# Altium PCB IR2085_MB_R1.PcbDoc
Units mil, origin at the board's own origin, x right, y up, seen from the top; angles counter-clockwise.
Board outline 6000 x 4000 mil, 2 copper layers (Top Layer, Bottom Layer); 79 components, 34 nets, 245 pads, 204 vias.
Unrouted connection lines stored in the file: 2.
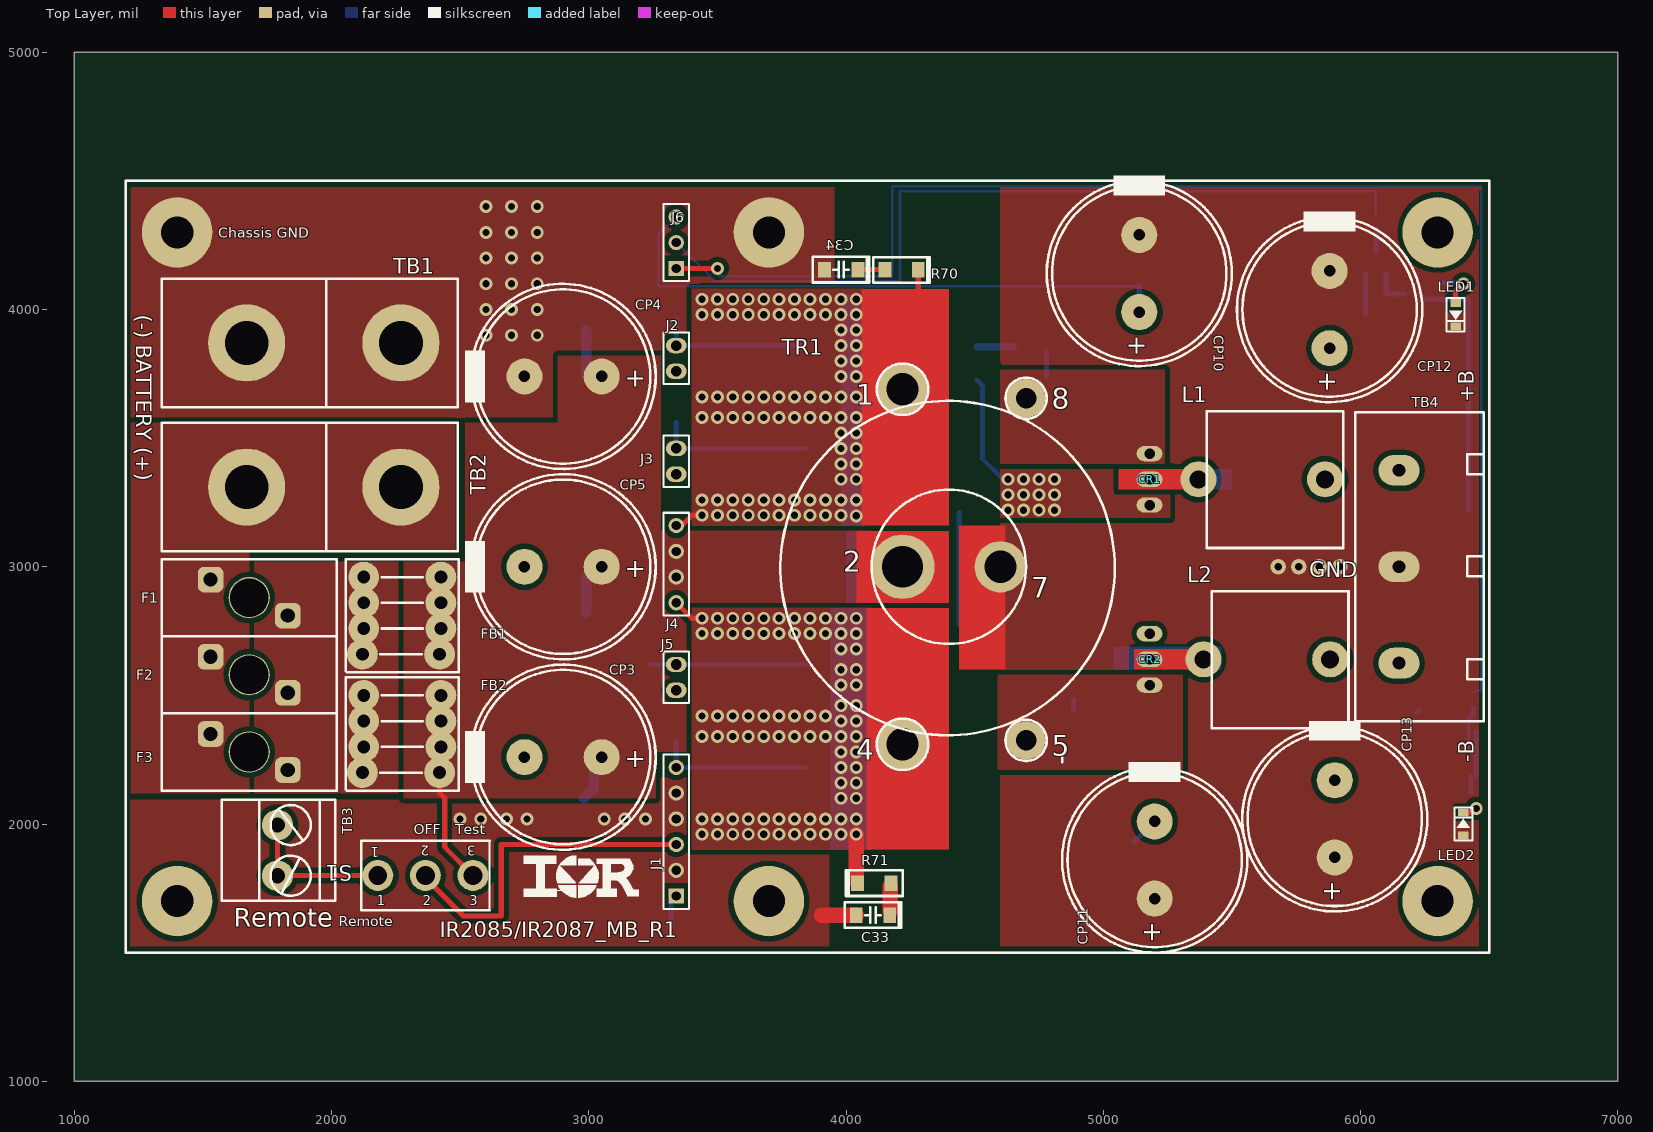
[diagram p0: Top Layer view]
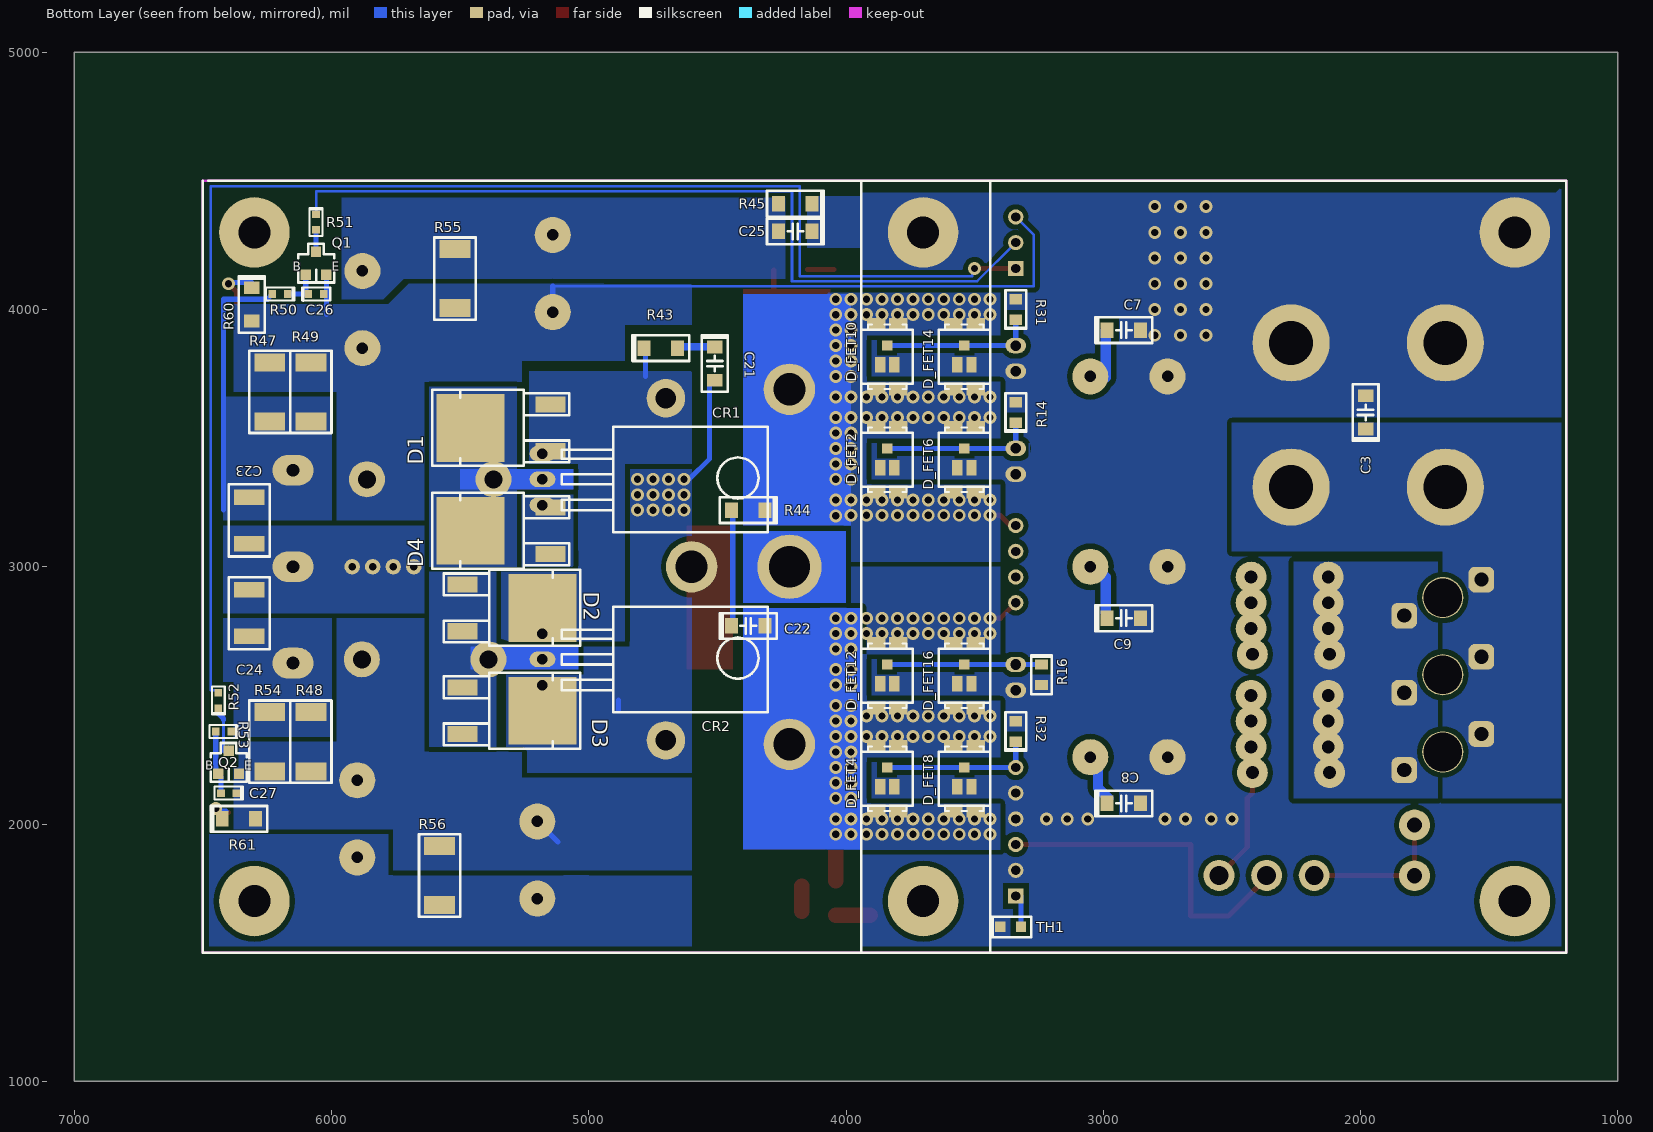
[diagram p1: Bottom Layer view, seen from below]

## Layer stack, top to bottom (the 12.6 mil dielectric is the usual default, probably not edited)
Top Layer: signal copper 1.4
Dielectric: dielectric 12.6, FR-4, Dk 4.8
Bottom Layer: signal copper 1.4

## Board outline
1000,1000 7000,1000 7000,5000 1000,5000

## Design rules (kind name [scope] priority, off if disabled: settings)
Clearance [All] p1: gap=20
ComponentClearance [All] p1: gap=10 collisioncheckmode=3 verticalgap=10
PlaneConnect [All] p1: planeconnectstyle=Direct reliefexpansion=20 reliefentries=4 reliefconductorwidth=10 reliefairgap=10
PolygonConnect [All] p1: connectstyle=Direct reliefconductorwidth=10 reliefentries=4 polygonreliefangle="90 Angle"
RoutingVias [All] p1: holewidth=28 width=38 viastyle="Through Hole" minholewidth=28 minwidth=38 maxholewidth=28 maxwidth=50
SolderMaskExpansion [All] p1: expansion=4
TestPointUsage [All] p1: valid=0 allowmultiple=FALSE
Testpoint [All] p1: side=15 testpointundercomponent=TRUE minsize=40 maxsize=100 preferedsize=60 minholesize=0 maxholesize=40 preferedholesize=32 testpointgrid=1 style=1023 order=0-112345678
Width [All] p1: maxlimit=40 minlimit=10 preferedwidth=20 toplayer_maxwidth=30 bottomlayer_maxwidth=30 minimp=50.000000 maximp=50.000000 favimp=50.000000
17 further rules are at their usual default settings.

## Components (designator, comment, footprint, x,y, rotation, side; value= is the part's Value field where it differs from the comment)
C3 "1uF" C-1206#1 1980,3600 r0 bottom
C7 "1uF" C-1206#1 2920,3920 r90 bottom
C8 "1uF" C-1206#1 2920,2080 r90 bottom
C9 "1uF" C-1206#1 2920,2800 r90 bottom (schematic designator C18)
C21 "C-1206" C-1206#1 4510,3790 r180 bottom
C22 "C-1206" C-1206#1 4380,2770 r90 bottom
C23 "1uF" 1812 6320,3180 r270 bottom
C24 "1uF" 1812 6320,2820 r270 bottom
C25 "C-1206" C-1206#1 4197,4304 r270 bottom
C26 "C-603" C-603 6060,4060 r90 bottom
C27 "C-603" C-603 6400,2120 r270 bottom
C33 "C-1206" C-1206#1 4105,1646 r270 top
C34 "C-1206" C-1206#2 3981,4155 r90 top
CP3 "CP7.5MMX16D" CP7.5MMX18D 2900,2260 r270 top
CP4 "CP7.5MMX16D" CP7.5MMX18D 2900,3740 r270 top
CP5 "CP7.5MMX16D" CP7.5MMX18D 2900,3000 r270 top
CP10 "CP7.5MMX18DX31H" CP7.5MMX18D 5140,4140 r180 top
CP11 "CP7.5MMX18DX31H" CP7.5MMX18D 5200,1860 r180 top
CP12 "CP7.5MMX18DX31H" CP7.5MMX18D 5880,4000 r180 top
CP13 "CP7.5MMX18DX31H" CP7.5MMX18D 5900,2020 r180 top
CR1 "TO220+RECT" TO220+RECT_BOT 5180,3340 r90 top
CR2 "TO220-RECT" TO220+RECT_BOT 5180,2640 r90 top
D1 "Dual Diode" "DPAK (TO-252)" 5460,3540 r90 bottom
D2 "Dual Diode" "DPAK (TO-252)" 5180,2840 r270 bottom
D3 "Dual Diode" "DPAK (TO-252)" 5180,2440 r270 bottom
D4 "Dual Diode" "DPAK (TO-252)" 5460,3140 r90 bottom
D_FET2 "IRF6648" IRF6648 3840,3420 r0 bottom
D_FET4 "IRF6648" IRF6648 3840,2180 r0 bottom
D_FET6 "IRF6648" IRF6648 3540,3420 r0 bottom
D_FET8 "IRF6648" IRF6648 3540,2180 r0 bottom
D_FET10 "IRF6648" IRF6648 3840,3820 r0 bottom
D_FET12 "IRF6648" IRF6648 3840,2580 r0 bottom
D_FET14 "IRF6648" IRF6648 3540,3820 r0 bottom
D_FET16 "IRF6648" IRF6648 3540,2580 r0 bottom
F1 "20A" FUSE-F065-ND_FUSE-F065-ND(Primary)#1 1680,2880 r90 top
F2 "20A" FUSE-F065-ND_FUSE-F065-ND(Primary)#2 1680,2580 r90 top
F3 "20A" FUSE-F065-ND_FUSE-F065-ND(Primary)#1 1680,2280 r90 top
FB1 "FB" FB300x4 2280,2860 r0 top
FB2 "FB" FB300x4 2280,2400 r0 top
J1 "Header 6H" HDR1X6 3340,1720 r90 top
J2 "Header 2" HDR1X2 3340,3760 r90 top
J3 "Header 2" HDR1X2 3340,3360 r90 top
J4 "Header 4" HDR1X4 3340,2860 r90 top
J5 "Header 2" HDR1X2 3340,2520 r90 top
J6 "Header 3" HDR1X3 3340,4160 r90 top
L1 "3.3uH" L-513-1522-ND 5660,3340 r0 top
L2 "3.3uH" L-513-1522-ND 5680,2640 r0 top
LED1 "+B" LED-805 6370,3980 r90 top
LED2 "-B" LED-805 6400,2000 r270 top
Q1 "SOT23-PNP" SOT23-PNP 6060,4180 r180 bottom
Q2 "SOT23-NPN" SOT23-NPN_SOT23-NPN(Primary) 6400,2240 r180 bottom
R14 "R-805" R-805 3340,3600 r90 bottom
R16 "R-805" R-805 3240,2580 r270 bottom
R31 "R-805" R-805 3340,4000 r90 bottom
R32 "R-805" R-805 3340,2360 r90 bottom
R43 "R-1206" R-1206 4720,3850 r0 bottom
R44 "R-1206" R-1206 4380,3220 r180 bottom
R45 "R-1206" R-1206 4197,4411 r180 bottom
R47 "R-2512" R-2512 6240,3680 r180 bottom
R48 "R-2512" R-2512 6080,2320 r0 bottom
R49 "R-2512" R-2512 6080,3680 r180 bottom
R50 "R-603" R-603 6200,4060 r180 bottom
R51 "R-603" R-603 6060,4340 r90 bottom
R52 "R-603" R-603 6440,2480 r270 bottom
R53 "R-603" R-603 6420,2360 r180 bottom
R54 "R-2512" R-2512 6240,2320 r0 bottom
R55 "R-2512" R-2512 5520,4120 r180 bottom (schematic designator R47)
R56 "R-2512" R-2512 5580,1800 r180 bottom (schematic designator R47)
R60 "R-1206" R-1206 6310,4019.74 r90 bottom
R61 "R-1206" R-1206 6360,2020 r0 bottom
R70 "R-1206" R-1206 4216,4154 r0 top
R71 "R-1206" R-1206 4110,1770 r180 top
S1 "3PSW" S1 2180,1800 r0 top
TB1 "TB" TB-Gold 1840,3620 r0 top
TB2 "TB" TB-Gold 1840,3060 r0 top
TB3 "277-1022-ND" "TB_277_1022_ND_Remote On/Off()" 1560,1900 r0 top (schematic designator TB2)
TB4 "277-1272" "J HEADER3" 6140,3000 r90 top (schematic designator J7)
TH1 "TH-805" TH-805 3360,1600 r180 bottom
TR1 "TR100" TR1300 4400,3000 r0 top

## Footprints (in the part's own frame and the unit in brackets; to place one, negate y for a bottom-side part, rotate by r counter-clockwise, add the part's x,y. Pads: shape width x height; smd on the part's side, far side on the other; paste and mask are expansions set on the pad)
1812 [mil] "SMD 1812"
  rect 60x120 smd: 1(-90,0) 2(90,0)
  silkscreen extent -140,-80 140,80
C-603 [mil]
  rect 30x30 smd: 1(0,30) 2(0,-30)
  silkscreen extent -25,-55 25,55
C-1206#1 [mil]
  rect 60x50 smd: 1(0,65) 2(0,-65)
  silkscreen extent -50,-110 50,110
C-1206#2 [mil]
  rect 60x50 smd: 1(0,-65) 2(0,65)
  silkscreen extent -50,-110 50,110
CP7.5MMX18D [mil]
  round 140 hole 45: 1(0,150) 2(0,-150)
  silkscreen extent -360,-380 360,360
"DPAK (TO-252)" [mm]
  rect 1.6x3 smd: 1(-2.3,-7.9) 3(2.3,-7.9)
  rect 6.7x6.7 smd: 2(0,0)
  silkscreen extent -3.75,-9.75 3.75,3.75
FB300x4 [mil] "Ferrite Bead x4"
  round 120 hole 50: 1(-155,100) 2(-155,0) 3(-155,-100) 4(-160,-200) 5(140,-200) 6(145,-100) 7(145,0) 8(145,100)
  silkscreen extent -225,-270 215,170
FUSE-F065-ND_FUSE-F065-ND(Primary)#1 [mil]
  rrect50% 100x100 hole 55: 1(70,150) 2(-70,-150)
  round 160 hole 150 unplated: Mounting1(0,0)
  silkscreen extent -150,-340 150,340
FUSE-F065-ND_FUSE-F065-ND(Primary)#2 [mil]
  rrect50% 100x100 hole 55: 1(70,150) 2(-70,-150)
  round 160 hole 149 unplated: Mounting1(0,0)
  silkscreen extent -150,-340 150,340
HDR1X2 [mil] "Connector; Header; 2 Position"
  oval 60x80 hole 41: 1(0,0) 2(100,0)
  silkscreen extent -50,-50 150,50
HDR1X3 [mm] "Connector; Header; 3 Position"
  rect 1.5x1.5 hole 0.9: 1(0,0)
  round 1.5 hole 0.9: 2(2.54,0) 3(5.08,0)
  silkscreen extent -1.27,-1.27 6.35,1.27
HDR1X4 [mm] "Connector; Header; 4 Position"
  round 1.5 hole 0.9: 1(0,0) 2(2.54,0) 3(5.08,0) 4(7.62,0)
  silkscreen extent -1.27,-1.27 8.89,1.27
HDR1X6 [mm] "Connector; Header; 2 Position"
  rect 1.5x1.5 hole 0.9: 1(0,0)
  round 1.5 hole 0.9: 2(2.54,0) 3(5.08,0) 4(7.62,0) 5(10.16,0) 6(12.7,0)
  silkscreen extent -1.27,-1.27 13.97,1.27
IRF6648 [mil]
  rect 40x40 smd: 1(0,-40)
  rect 72x50 smd: 2(-44,-122) 4(43,-122) 6(-44,129) 7(43,129)
  rect 40x60 smd: 3(27,35) 5(-28,35)
  silkscreen extent -100,-121 100,129
"J HEADER3" [mil]
  oval 120x160 hole 50: 1(0.15,-10) 2(374.95,-10) 3(-374.66,-10)
  silkscreen extent -601,-340 601,160
L-513-1522-ND [mil] "3.3uH/10A"
  round 140 hole 70: 1(-290,0) 2(202.13,0)
  silkscreen extent -258,-267 273,265
LED-805 [mil]
  rect 30x40 smd: 1(-45,0) 2(45,0)
  silkscreen extent -65,-35 65,35
R-603 [mil]
  rect 30x30 smd: 1(30,0) 2(-30,0)
  silkscreen extent -55,-25 55,25
R-805 [mil]
  rect 40x50 smd: 1(-40,0) 2(40,0)
  silkscreen extent -75,-40 75,40
R-1206 [mil]
  rect 50x60 smd: 1(65,0) 2(-65,0)
  silkscreen extent -110,-50 110,50
R-2512 [mil]
  rect 120x70 smd: 1(0,115) 2(0,-115)
  silkscreen extent -80,-160 80,160
S1 [mil]
  round 120 hole 73: 1(0,0) 2(185,0) 3(370,0)
  silkscreen extent -65,-135 435,135
SOT23-NPN_SOT23-NPN(Primary) [mil]
  rect 40x40 smd: B(-40,-45) C(0,45) E(40,-45)
  silkscreen extent -70,-75 70,75
SOT23-PNP [mil]
  rect 40x40 smd: 1(-40,-45) 2(40,-45) 3(0,45)
  silkscreen extent -70,-75 70,75
TB-Gold [mil] "Terminal Block # 8 AWG gold Audio Express P/N 070-850"
  round 300 hole 170: 1(-170,250) 2(430,250)
  silkscreen extent -500,0 650,500
"TB_277_1022_ND_Remote On/Off()" [mil]
  round 120 hole 60: 1(230,96) 2(230,-101)
  silkscreen extent 13,-199 454,194
TH-805 [mil]
  rect 40x40 smd: 1(-40,0) 2(40,0)
  silkscreen extent -80,-40 80,40
TO220+RECT_BOT [mil]
  oval 60x100 hole 41: 1(-100,0) 2(0,0) 3(100,0)
TR1300 [mil]
  round 200 hole 125: 1(-180,690) 4(-180,-690) 7(200,0)
  round 250 hole 160: 2(-180,0)
  round 150 hole 80: 5(300,-675) 8(300,655)
  silkscreen extent -655,-790 645,790

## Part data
C3 C7 C8 C9 C23 C24: library part CAP, "CBB"
C34: "CAP 1000PF 100V CERAMIC X7R 1206"
CP10 CP11 CP12 CP13: library part CP7.5MMX16D, "CP7.5MMX16D"
D_FET2 D_FET4 D_FET6 D_FET8 D_FET10 D_FET12 D_FET14: library part IRF6645, "IRF6645"
F1 F2 F3: library part FUSE2, "Fuse"
FB1 FB2: library part FB_8A_SMT, "FB_8A_SMT"
J4: "Header, 4-Pin"
LED1 LED2: library part LED-805, "LED 468NM BLUE CLEAR 0805 SMD"
R43 R44 R45 R70: library part R-805, "R-805"
R60 R61: library part R-805, "RES 1.0K OHM 1/4W 5% 1206 SMD"
R71: library part R-805, "RES 10 OHM 1/4W 5% 1206 SMD"
S1: library part SW_T80-T, "SW_T80-T"
TB3: library part TB-ED2354-ND, "TB-ED2354-ND"
TB4: library part CONN3

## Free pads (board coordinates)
  round 60 hole 30: 0(5920,3000) 1(5840,3000) 2(5760,3000) 3(5680,3000) 4(5680,3000)
  round 274 hole 125: 4(1400,1700) 4(1400,4300) 4(3700,1700) 4(3700,4300) 4(6300,1700) 4(6300,4300)

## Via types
v1: diameter 50, hole 28, Top Layer to Bottom Layer, tented both sides, 179 vias
v2: diameter 50, hole 28, Top Layer to Bottom Layer, 25 vias

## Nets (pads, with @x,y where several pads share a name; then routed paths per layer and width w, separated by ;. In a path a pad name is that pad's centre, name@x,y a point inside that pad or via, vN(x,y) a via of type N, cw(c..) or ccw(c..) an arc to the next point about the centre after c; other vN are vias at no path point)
14.4V: C7.1 C8.1 C9.1 CP3.1 CP4.1 CP5.1 FB1.5 FB1.6 FB1.7 FB1.8 FB2.5 FB2.6 FB2.7 FB2.8 J4.2 J4.3 S1.3 TR1.2 | length 1131.7
  Top Layer w20: FB2.5 2420,2120 2440,2100 2440,1910 S1.3
  Bottom Layer w20: 2990,2960 CP5.1@3030,3000 ; CP4.1@3015.36,3725.36 CP4.1@3030,3740 ; CP3.1@3020,2290 CP3.1
  Bottom Layer w40: C8.1@2980,2100 3020,2140 CP3.1@3020,2290 ; C9.1@2990,2820 2990,2960 ; C7.1@2990,3920 2990,3735.86 CP4.1@3015.36,3725.36
+B: C26.2 CP10.1 CP12.1 J6.3 L1.2 Q1.2 R47.1 R49.1 R60.2 | length 2424
  Bottom Layer w10: J6.3 3270,4290 3270,4090.39 5140,4090.39
  Bottom Layer w20: CP10.1 5140,4090.39 ; 6020,3980 Q1.2
+BATTERY: C3.1 F1.1 F2.1 F3.1 TB2.1 TB2.2
+V: C23.1 R47.2 R49.2 R50.2 TB4.2 | length 1018.3
  Bottom Layer w20: R50.2 6250,4040 6420,4040 6420,3220
+V_RECTIFIED: CR1.2 D1.2 D4.2 L1.1
-B: C27.1 CP11.2 CP13.2 L2.2 Q2.E R48.1 R54.1 R61.2 | length 113.1
  Bottom Layer w20: 5120,1930 CP11.2
-V: C24.2 R48.2 R53.1 R54.2 TB4.3 | length 7.1
  Bottom Layer w20: R54.2@6220,2435 R54.2@6225,2440
-V_RECTIFIED: CR2.2 D2.1 D2.3 D3.1 D3.3 L2.1
GND: C3.2 C7.2 C8.2 C9.2 C25.1 C33.2 C34.2 CP3.2 CP4.2 CP5.2 D_FET2.3 D_FET2.5 D_FET4.3 D_FET4.5 D_FET6.3 D_FET6.5 D_FET8.3 D_FET8.5 D_FET10.3 D_FET10.5 D_FET12.3 D_FET12.5 D_FET14.3 D_FET14.5 D_FET16.3 D_FET16.5 J1.2 J1.4 J1.5 J2.1 J3.1 J5.1 pad.4@1400,4300 pad.4@3700,4300 R14.2 R16.2 R31.2 R32.2 R45.1 TB1.1 TB1.2 TH1.1 | length 134
  Top Layer w60: 3906,1646 C33.2
  other v2: 2500,2020 2580,2020 2680,2020 2760,2020 3060,2020 3140,2020 3220,2020 2600,3900 2700,3900 2800,3900 2600,4000 2700,4000 2800,4000 2600,4100 2700,4100 2800,4100 2600,4200 2700,4200 2800,4200 2600,4300 2700,4300 2800,4300 2600,4400 2700,4400 2800,4400
LO1A: D_FET2.1 D_FET6.1 J3.2 R14.1 | length 600
  Bottom Layer w20: R14.1 J3.2 D_FET2.1
LO1B: D_FET10.1 D_FET14.1 J2.2 R31.1 | length 600
  Bottom Layer w20: R31.1 J2.2 D_FET10.1
LO2A: D_FET12.1 D_FET16.1 J5.2 R16.1 | length 600
  Bottom Layer w20: R16.1 D_FET12.1
LO2B: D_FET4.1 D_FET8.1 J1.6 R32.1 | length 600
  Bottom Layer w20: R32.1 J1.6 D_FET4.1
NetC21_1: C21.1 R43.2 | length 140
  Bottom Layer w30: C21.1 R43.2@4650,3855
NetC22_1: C22.1 R44.2 | length 442.1
  Bottom Layer w20: R44.2@4440,3210 4440,2775 C22.1
NetC26_1: C26.1 Q1.1 R50.1 | length 145
  Bottom Layer w20: Q1.1 6100,4060 R50.1
NetC27_2: C27.2 Q2.B R53.2 | length 235
  Bottom Layer w20: C27.2 Q2.B@6430,2185 ; Q2.B@6450,2190 R53.2
NetC33_1: C33.1 R71.2 | length 99
  Top Layer w60: C33.1@4172,1660 R71.2@4172,1759
NetC34_1: C34.1 R70.2 | length 104
  Top Layer w20: C34.1 R70.2@4150,4155
NetF1_2: F1.2 F2.2 F3.2 FB1.1 FB1.2 FB1.3 FB1.4 FB2.1 FB2.2 FB2.3 FB2.4
NetJ1_1: J1.1 TH1.2 | length 122.9
  Bottom Layer w20: TH1.2 J1.1@3320,1720 ; J1.1@3340,1717.12 J1.1
NetJ1_3: J1.3 S1.2 | length 1299.5
  Top Layer w20: S1.2@2375,1780 2512.5,1642.5 2660,1642.5 2660,1920 J1.3
NetLED1_2: LED1.2 R60.1 | length 172.4
  Top Layer w20: LED1.2 6370,4070 v1(6400,4100)
  Bottom Layer w20: R60.1@6310,4105 v1@6395,4105
NetLED2_1: LED2.1 R61.1 | length 118.6
  Top Layer w20: LED2.1 6435,2045 v1(6450,2060)
  Bottom Layer w20: 6410,2050 v1@6430,2050 ; R61.1@6420,2030 v1(6450,2060)
NetQ1_3: Q1.3 R51.2 | length 85
  Bottom Layer w20: Q1.3 R51.2
NetQ2_C: Q2.C R52.1 | length 68.5
  Bottom Layer w10: Q2.C Q2.C@6400,2300.19
  Bottom Layer w20: 6420,2405 6420,2410 6440,2430 R52.1
NetS1_1: S1.1 TB3.1 TB3.2 | length 597
  Top Layer w20: TB3.2@1780,1800 S1.1 ; TB3.2 TB3.1
SCP+: J6.2 R51.1 | length 3222.1
  Bottom Layer w10: J6.2 3490,4110 4210,4110 4210,4460 6060,4460 R51.1
SCP-: J6.1 R52.2 | length 5498.3
  Top Layer w20: J6.1 v1(3500,4160)
  Bottom Layer w10: v1(3500,4160) 3510,4150 3510,4130 4180,4130 4180,4480 6470,4480 6470,2520 6450,2520 R52.2
SGND: C23.2 C24.1 C25.2 CP10.2 CP11.1 CP12.2 CP13.1 LED1.1 LED2.2 pad.0 pad.1 pad.2 pad.3 pad.4@5680,3000 R45.2 TB4.1 TR1.7
SW1: CR1.3 CR2.3 D1.1 D1.3 D2.2 R43.1 TR1.8 | length 100
  Bottom Layer w20: 4780,3740 R43.1@4780,3840
SW2: C21.2 CR1.1 CR2.1 D3.2 D4.1 D4.3 TR1.5 | length 466.4
  Bottom Layer w20: C21.2 4530,3705 4530,3420 v1@4610,3340 ; 4885,2441 4885,2481
  other v1: 4630,3220 4690,3220 4750,3220 4810,3220 4630,3280 4690,3280 4750,3280 4810,3280 4630,3340 4690,3340 4750,3340 4810,3340
VS1: C22.2 D_FET4.2 D_FET4.4 D_FET4.6 D_FET4.7 D_FET8.2 D_FET8.4 D_FET8.6 D_FET8.7 D_FET12.2 D_FET12.4 D_FET12.6 D_FET12.7 D_FET16.2 D_FET16.4 D_FET16.6 D_FET16.7 J4.1 R71.1 TR1.4 | length 304.9
  Top Layer w20: J4.1 3400,2800 v1(3440,2800)
  Top Layer w60: R71.1@4040,1780 v1(4040,1960)
  other v1: 3440,1960 3500,1960 3560,1960 3620,1960 3680,1960 3740,1960 3800,1960 3860,1960 3920,1960 3980,1960 3440,2020 3500,2020 3560,2020 3620,2020 3680,2020 3740,2020 3800,2020 3860,2020 3920,2020 3980,2020 4040,2020 3980,2100 4040,2100 3980,2160 4040,2160 3980,2220 4040,2220 3980,2280 4040,2280 3440,2340 3500,2340 3560,2340 3620,2340 3680,2340 3740,2340 3800,2340 3860,2340 3920,2340 3980,2340 4040,2340 3980,2400 4040,2400 3440,2420 3500,2420 3560,2420 3620,2420 3680,2420 3740,2420 3800,2420 3860,2420 3920,2420 3980,2460 4040,2460 3980,2540 4040,2540 3980,2600 4040,2600 3980,2680 4040,2680 3440,2740 3500,2740 3560,2740 3620,2740 3680,2740 3740,2740 3800,2740 3860,2740 3920,2740 3980,2740 4040,2740 3500,2800 3560,2800 3620,2800 3680,2800 3740,2800 3800,2800 3860,2800 3920,2800 3980,2800 4040,2800
VS2: D_FET2.2 D_FET2.4 D_FET2.6 D_FET2.7 D_FET6.2 D_FET6.4 D_FET6.6 D_FET6.7 D_FET10.2 D_FET10.4 D_FET10.6 D_FET10.7 D_FET14.2 D_FET14.4 D_FET14.6 D_FET14.7 J4.4 R44.1 R70.1 TR1.1 | length 249.6
  Top Layer w20: J4.4 3361.14,3160 3401.14,3200 v1(3440,3200) ; 4281,4021 R70.1
  other v1: 3500,3200 3560,3200 3620,3200 3680,3200 3740,3200 3800,3200 3860,3200 3920,3200 3980,3200 3440,3260 3500,3260 3560,3260 3620,3260 3680,3260 3740,3260 3800,3260 3860,3260 3920,3260 3980,3260 4040,3260 3980,3340 4040,3340 3980,3400 4040,3400 3980,3460 4040,3460 3980,3520 4040,3520 3440,3580 3500,3580 3560,3580 3620,3580 3680,3580 3740,3580 3800,3580 3860,3580 3920,3580 3980,3580 4040,3580 3440,3660 3500,3660 3560,3660 3620,3660 3680,3660 3740,3660 3800,3660 3860,3660 3920,3660 3980,3660 4040,3660 3980,3740 4040,3740 3980,3800 4040,3800 3980,3860 4040,3860 3980,3920 4040,3920 3440,3980 3500,3980 3560,3980 3620,3980 3680,3980 3740,3980 3800,3980 3860,3980 3920,3980 3980,3980 4040,3980 3440,4040 3500,4040 3560,4040 3620,4040 3680,4040 3740,4040 3800,4040 3860,4040 3920,4040 3980,4040 4040,4040
pads on no net: F1.Mounting1 F2.Mounting1 F3.Mounting1 R55.1 R55.2 R56.1 R56.2
copper on no net: | length 125
  Bottom Layer w10: 6420,2280 6420,2405
  other v1: 4040,3198

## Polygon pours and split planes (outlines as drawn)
SGND on Top Layer (solid, remove dead copper): 6480,4480 6460,4460 6460,1520 4600,1520 4600,4480
SW2 on Top Layer "Top Layer-SW2" (solid, pour order 1001): 5310,2580 4590,2580 4590,2210 5310,2210
SW1 on Top Layer "Top Layer-SW1" (solid, pour order 1000): 5240,3400 5240,3765.77 4604.58,3765.77 4600,3770 4600,3400.86
GND on Top Layer "Top Layer-GND 2" (solid, pour order 1000): 3280,2180 3380,2180 3380,1960 3280,1960
VS1 on Top Layer "Top Layer-VS1" (solid, pour order 1000): 3400,2840 4100,2840 4100,1900 3400,1900
VS2 on Top Layer "Top Layer-VS2" (solid, pour order 1001): 3400,4080 4070,4080 4070,3160 3400,3160
SW2 on Top Layer "Top Layer-SW2 1" (solid, pour order 1007): 4600,3190 4600,3380 5040,3380 5040,3280 5260,3280 5260,3190
GND on Top Layer "Top Layer-GND" (solid, pour order 1001): 1220,4485.58 1220,3580 2868.69,3580 2868.69,3821.49 3431.66,3821.49 3431.66,4103.22 3954.42,4103.22 3954.42,4485.58
NetF1_2 on Top Layer "Top Layer-NetF1_2" (solid, pour order 1001): 2260,3020 2260,2120 1700,2120 1700,3020
+BATTERY on Top Layer "Top Layer-+BATTERY" (solid, pour order 1000): 2480,3560 2480,3060 1680,3060 1680,2120 1220,2120 1220,3560
GND on Top Layer "Top Layer-GND 1" (solid, remove dead copper, pour order 1002): 1214.03,2094.42 1214.03,1514.71 3934.03,1514.71 3934.03,2094.42
14.4V on Top Layer "Top Layer-14.4V" (solid, pour order 1002): 4100,3140 4100,2860 3380,2860 3380,2280 3260,2280 3260,2100 2280,2100 2280,3020 2520,3020 2520,3560 2880,3560 2880,3820 3280,3820 3280,3140
SW2 on Bottom Layer "Bottom Layer-SW2 1" (solid, pour order 1004): 4855,2502 4855,2433 5079,2433 5081,2431 5081,2501
SW2 on Bottom Layer "Bottom Layer-SW2" (solid, pour order 1003): 5060,3000 5259.57,3000 5259.87,3000.65 5259.87,3280 5061.36,3280 5060.91,3279
SW1 on Bottom Layer "Bottom Layer-SW1" (solid, pour order 1002): 4860,3420 5040,3420 5040,2980 5340,2980 5340,2720.78 5339.61,2720.39 5310,2710 4860,2710
NetF1_2 on Bottom Layer "Bottom Layer-NetF1_2" (solid, pour order 1008): 1700,2100 2260,2100 2260,3020 1700,3020
+BATTERY on Bottom Layer "Bottom Layer-+BATTERY" (solid, pour order 1007): 2500,3560 1220,3560 1220,2100 1680,2100 1680,3060 2500,3060
+B on Bottom Layer "Bottom Layer-NetC26_2" (solid, pour order 1003): 6380,3680 5980,3680 5980,3180 5640,3180 5640,3720 5260,3720 5260,3800 4860,3800 4860,3940 4600,3940 4600,4100 5700,4100 5780,4020 6380,4020
-B on Bottom Layer "Bottom Layer-NetC27_1" (solid, pour order 1002): 6360,2320 6360,2220 6380,2220 6380,1980 5760,1980 5760,1820 4600,1820 4600,2180 5260,2180 5260,2280 5640,2280 5640,2800 5980,2800 5980,2320
-V on Bottom Layer "Bottom Layer--V" (solid, pour order 1001): 6000,2800 6420,2800 6420,2552.31 6380,2552.31 6380,2340 6000,2340
+V on Bottom Layer "Bottom Layer-+V" (solid, pour order 1000): 6000,3180 6420,3180 6420,3660 6000,3660
VS1 on Bottom Layer "Bottom Layer-VS1" (solid, pour order 1000): 4000,2840 4100,2840 4100,2700 4000,2700
VS1 on Bottom Layer "Bottom Layer-VS1 2" (solid, pour order 1019): 3400,3000 3980,3000 3980,2840 4100,2840 4100,2700 4000,2700 4010,2660 3400,2660
VS1 on Bottom Layer "Bottom Layer-VS1 4" (solid, pour order 1021): 3400,2080 3400,1900 4070,1900 4070,2080
GND on Bottom Layer "Bottom Layer-GND 3" (solid, pour order 1003): 3900,2499.61 3140,2499.61 3140,2639.61 3900,2639.61
GND on Bottom Layer "Bottom Layer-GND 2" (solid, pour order 1002): 3900,2099.61 3140,2099.61 3140,2239.61 3900,2239.61
VS1 on Bottom Layer "Bottom Layer-VS1 3" (solid, pour order 1020): 3400,2480 4070,2480 4070,2260 3400,2260
VS2 on Bottom Layer "Bottom Layer-VS2 1" (solid, pour order 1008): 3400,3720 4070,3720 4070,3500 3400,3500
GND on Bottom Layer "Bottom Layer-GND 1" (solid, pour order 1001): 3900,3340 3240,3340 3240,3480 3900,3480
-V_RECTIFIED on Bottom Layer "Bottom Layer--V_RECTIFIED 1" (solid, pour order 1022): 5360,2980 5360,2300 5620,2300 5620,2980
+V_RECTIFIED on Bottom Layer "Bottom Layer-+V_RECTIFIED 4" (solid, pour order 1021): 5280,3700 5620,3700 5620,3000 5280,3000
VS1 on Bottom Layer "Bottom Layer-VS1 7" (solid, pour order 1024): 4010,2660 3920,2660 3920,2480 4010,2480
VS1 on Bottom Layer "Bottom Layer-VS1 6" (solid, pour order 1023): 4070,2260 3920,2260 3920,2080 4070,2080
VS2 on Bottom Layer "Bottom Layer-VS2 7" (solid, pour order 1014): 4070,3320 3920,3320 3920,3500 4070,3500
VS2 on Bottom Layer "Bottom Layer-VS2 6" (solid, pour order 1013): 4070,3900 4070,3720 3920,3720 3920,3900
VS2 on Bottom Layer "Bottom Layer-VS2 2" (solid, pour order 1009): 3400,3320 4070,3320 4070,3160 3980,3160 3980,3020 3400,3020
GND on Bottom Layer "Bottom Layer-GND" (solid, pour order 1000): 3900,3740 3240,3740 3240,3880 3900,3880
SGND on Bottom Layer "Bottom Layer-SGND" (solid, pour order 1005): 5640,3160 6420,3160 6420,2820 5640,2820
SGND on Bottom Layer "Bottom Layer-SGND 2" (solid, pour order 1002): 6480,1520 4600,1520 4600,1800 5780,1800 5780,1960 6480,1960
SW2 on Bottom Layer "Bottom Layer-SW2 3" (solid, pour order 1020): 5320,2200 4600,2200 4600,2580 5320,2580
GND on Bottom Layer "Bottom Layer-GND 4" (solid, remove dead copper, pour order 1003): 1220,4473.52 1240,4453.52 3940,4453.52 3940,1513.52 1220,1513.52
SW1 on Bottom Layer "Bottom Layer-SW1 2" (solid, pour order 1006): 4600,3760 5240,3760 5230.56,3754.16 5230.56,3401.39 4624.17,3401.39 4621.92,3400 4600.41,3400
SGND on Bottom Layer "Bottom Layer-SGND 1" (solid, pour order 1001): 4210,4450 4210,4120 5720,4120 5800,4040 5960,4040 5960,4450
GND on Bottom Layer "Bottom Layer-No Net" (solid, pour order 1000): 3849.97,4440 4149.97,4440 4149.97,4240 3849.97,4240
VS2 on Bottom Layer "Bottom Layer-VS2" (solid, pour order 1007): 3400,4080 4070,4080 4070,3900 3400,3900
SW2 on Bottom Layer "Bottom Layer-SW2 2" (solid, pour order 1000): 4600,3380 4840,3380 4840,2690 5020,2690 5020,2580 4600,2580

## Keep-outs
Keep-Out Layer:
  lines w10: 1200,1500 6500,1500 6500,4500 1200,4500 1200,1500

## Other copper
Top Layer:
  rectangle net +V_RECTIFIED: 5060,3300 5400,3380
  rectangle: 5120,2600 5440,2680
  rectangle net SGND: 4440,2600 4620,3160
  rectangle net VS1: 4080,1900 4400,2840
  rectangle net 14.4V: 4040,2860 4400,3140
  rectangle net VS2: 4060,3160 4400,4080
Bottom Layer:
  rectangle net 14.4V: 4000,2860 4400,3140
  rectangle net VS2: 3980,3160 4400,4060
  rectangle: 3940,1900 4400,2840
  rectangle net +V_RECTIFIED: 5060,3300 5500,3380
  rectangle net -V_RECTIFIED: 5040,2600 5460,2690

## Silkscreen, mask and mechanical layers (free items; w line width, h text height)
Top Overlay:
  drawing of 354 lines, arcs and shapes, not listed
  text "Chassis GND" at 1560,4280 h40
  text "(-) BATTERY (+)" at 1240,3980 h60 r270
  text "+B" at 6440,3640 h60 r90
  text "GND" at 5800,2960 h60
  text "-B" at 6440,2240 h60 r90
  text "OFF" at 2320,1960 h40
  text "Test" at 2480,1960 h40
  text "Remote" at 2028,1603 h40
  text "IR2085/IR2087_MB_R1" at 2420,1560 h60
Bottom Overlay:
  lines w10: 3440,1500 3440,4500 ; 3940,1500 3940,4500 ; 6480,4500 1200,4500 1200,1500 6500,1500 6500,4500
Top Solder:
  rectangle: 5000,2820 5500,3140
  rectangle: 4840,2300 5240,2520
  rectangle: 4840,3460 5220,3660
  rectangle: 3420,2380 4060,2820
  rectangle: 3420,2880 3940,3120
  rectangle: 3420,3180 4060,3620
